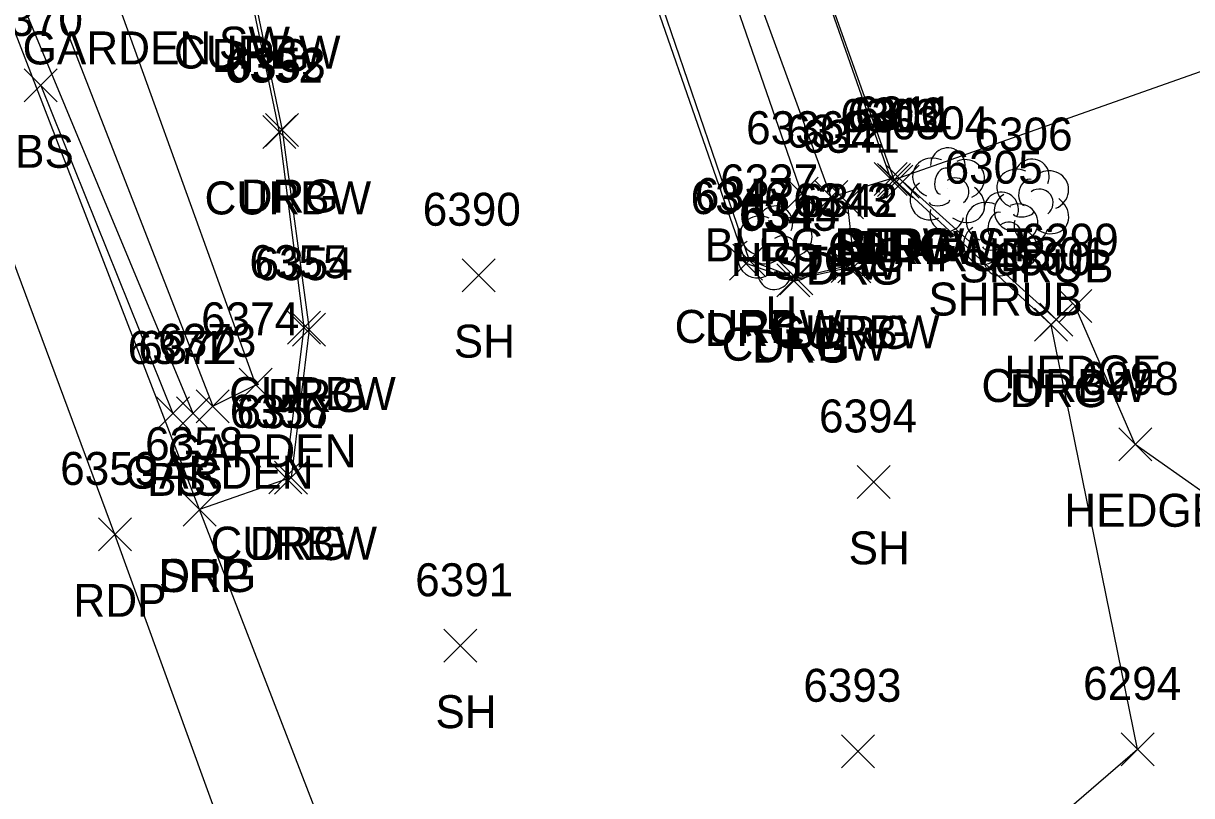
# Model space of a CAD drawing. Extents: x 1769141 to 1770911, y 735471 to 741449.
# Drawn here: x 1770299.5 to 1770370.4, y 740558.9 to 740605.8 of the extents above; entities that cross this region are included whole.
import ezdxf

# ---------------------------------------------------------------- set-up
doc = ezdxf.new("R2010")
doc.units = 0
for name, color, linetype in [('L_A', 7, 'Continuous'), ('L_I', 7, 'Continuous'), ('L_TIC', 7, 'Continuous'), ('LAHR', 7, 'Continuous'), ('LAPB', 7, 'Continuous'), ('LBC', 7, 'Continuous'), ('LBF', 7, 'Continuous'), ('LELB', 7, 'Continuous'), ('LSH', 7, 'Continuous'), ('LSOGP', 7, 'Continuous'), ('LTD', 7, 'Continuous'), ('P_A', 7, 'Continuous'), ('P_I', 7, 'Continuous'), ('P_TIC', 7, 'Continuous'), ('PET', 7, 'Continuous'), ('PSP', 7, 'Continuous'), ('R_A', 7, 'Continuous'), ('R_I', 7, 'Continuous'), ('R_TIC', 7, 'Continuous'), ('RC', 7, 'Continuous'), ('RDG', 7, 'Continuous')]:
    doc.layers.add(name, color=color, linetype=linetype)

msp = doc.modelspace()

# ---------------------------------------------------------------- linework, layer by layer
at = {"layer": 'L_TIC'}
for points in [[(1770299.573, 740601), (1770301.573, 740603)], [(1770301.573, 740601), (1770299.573, 740603)], [(1770351.112, 740595.326), (1770353.112, 740597.326)], [(1770353.112, 740595.326), (1770351.112, 740597.326)], [(1770351.112, 740595.326), (1770353.112, 740597.326)], [(1770353.112, 740595.326), (1770351.112, 740597.326)], [(1770351.319, 740595.262), (1770353.319, 740597.262)], [(1770353.319, 740595.262), (1770351.319, 740597.262)], [(1770345.708, 740594.432), (1770347.708, 740596.432)], [(1770347.708, 740594.432), (1770345.708, 740596.432)], [(1770347.511, 740594.223), (1770349.511, 740596.223)], [(1770349.511, 740594.223), (1770347.511, 740596.223)], [(1770326.129, 740589.486), (1770328.129, 740591.486)], [(1770328.129, 740589.486), (1770326.129, 740591.486)], [(1770362.306, 740587.614), (1770364.306, 740589.614)], [(1770364.306, 740587.614), (1770362.306, 740589.614)], [(1770312.605, 740582.838), (1770314.605, 740584.838)], [(1770314.605, 740582.838), (1770312.605, 740584.838)], [(1770310.001, 740581.536), (1770312.001, 740583.536)], [(1770312.001, 740581.536), (1770310.001, 740583.536)], [(1770307.585, 740581.101), (1770309.585, 740583.101)], [(1770309.585, 740581.101), (1770307.585, 740583.101)], [(1770308.796, 740581.109), (1770310.796, 740583.109)], [(1770310.796, 740581.109), (1770308.796, 740583.109)], [(1770365.938, 740579.227), (1770367.938, 740581.227)], [(1770367.938, 740579.227), (1770365.938, 740581.227)], [(1770350.071, 740576.947), (1770352.071, 740578.947)], [(1770352.071, 740576.947), (1770350.071, 740578.947)], [(1770325.018, 740567.011), (1770327.018, 740569.011)], [(1770327.018, 740567.011), (1770325.018, 740569.011)], [(1770349.121, 740560.611), (1770351.121, 740562.611)], [(1770351.121, 740560.611), (1770349.121, 740562.611)]]:
    msp.add_lwpolyline(points, dxfattribs=at)
at = {"layer": 'LAHR'}
for points in [[(1770339.44, 740616.413), (1770346.708, 740595.432)], [(1770381.293, 740570.108), (1770366.938, 740580.227), (1770363.306, 740588.614)]]:
    msp.add_lwpolyline(points, dxfattribs=at)
at = {"layer": 'LAPB'}
msp.add_lwpolyline([(1770292.169, 740641.437), (1770289.154, 740640.674), (1770298.462, 740614.818), (1770311.001, 740582.536), (1770313.605, 740583.838), (1770304.802, 740608.272), (1770322.28, 740615.018), (1770320.99, 740618.23), (1770303.138, 740612.542)], dxfattribs=at)
at = {"layer": 'LBC'}
msp.add_lwpolyline([(1770379.068, 740605.704), (1770352.319, 740596.262), (1770352.112, 740596.326), (1770340.804, 740628.648), (1770332.856, 740651.566), (1770359.461, 740660.913)], dxfattribs=at)
at = {"layer": 'LBF'}
msp.add_lwpolyline([(1770352.112, 740596.326), (1770348.511, 740595.223), (1770340.416, 740617.351), (1770339.502, 740617.408), (1770339.247, 740618.645), (1770334.568, 740617.183), (1770332.207, 740624.032), (1770336.61, 740625.673), (1770336.056, 740626.939), (1770340.804, 740628.648)], dxfattribs=at)
at = {"layer": 'LELB'}
for points in [[(1770296.256, 740614.633), (1770309.796, 740582.109)], [(1770300.573, 740602), (1770308.585, 740582.101)]]:
    msp.add_lwpolyline(points, dxfattribs=at)
at = {"layer": 'LSH'}
for p, q in [((1770355.53, 740595.726), (1770355.53, 740595.726)), ((1770355.53, 740595.726), (1770355.53, 740595.726)), ((1770360.633, 740595.048), (1770360.633, 740595.048)), ((1770360.633, 740595.048), (1770360.633, 740595.048)), ((1770358.769, 740593.039), (1770358.769, 740593.039)), ((1770358.769, 740593.039), (1770358.769, 740593.039))]:
    msp.add_line(p, q, dxfattribs=at)
for centre in [(1770355.577, 740597.16), (1770360.68, 740596.482), (1770358.816, 740594.473)]:
    msp.add_arc(centre, 1.047, 335.52715, 180.95627, dxfattribs=at)
for centre, major_axis, ratio, start_param, end_param in [((1770354.738, 740596.392), (1.21, -0.512), 0.895232, 1.570796, 4.712389), ((1770356.572, 740596.309), (-1.141, -0.483), 0.949671, 1.570796, 4.712389), ((1770355.322, 740596.184), (-0.208, -0.792), 0.645439, 3.141593, 6.283185), ((1770359.841, 740595.714), (1.21, -0.512), 0.895232, 1.570796, 4.712389), ((1770361.674, 740595.631), (-1.141, -0.483), 0.949671, 1.570796, 4.712389), ((1770354.447, 740595.017), (0.584, -1.042), 0.959034, 3.141593, 6.283185), ((1770356.03, 740595.559), (-0.5, 0.667), 0.989748, 3.141593, 6.283185), ((1770360.424, 740595.506), (-0.208, -0.792), 0.645439, 3.141593, 6.283185), ((1770356.53, 740594.893), (-1.09, 0.792), 0.841452, 1.570796, 4.712389), ((1770359.55, 740594.339), (0.584, -1.042), 0.959034, 3.141593, 6.283185), ((1770361.133, 740594.881), (-0.5, 0.667), 0.989748, 3.141593, 6.283185), ((1770355.072, 740594.976), (-0.625, -0.083), 0.423636, 0, 3.141593), ((1770357.977, 740593.706), (1.21, -0.512), 0.895232, 1.570796, 4.712389), ((1770359.811, 740593.623), (-1.141, -0.483), 0.949671, 1.570796, 4.712389), ((1770361.633, 740594.215), (-1.09, 0.792), 0.841452, 1.570796, 4.712389), ((1770355.53, 740594.226), (0.265, 1.061), 0.942809, 1.570796, 4.712389), ((1770358.561, 740593.498), (-0.208, -0.792), 0.645439, 3.141593, 6.283185), ((1770360.175, 740594.298), (-0.625, -0.083), 0.423636, 0, 3.141593), ((1770357.686, 740592.331), (0.584, -1.042), 0.959034, 3.141593, 6.283185), ((1770359.269, 740592.873), (-0.5, 0.667), 0.989748, 3.141593, 6.283185), ((1770360.633, 740593.548), (0.265, 1.061), 0.942809, 1.570796, 4.712389), ((1770359.769, 740592.206), (-1.09, 0.792), 0.841452, 1.570796, 4.712389), ((1770358.311, 740592.289), (-0.625, -0.083), 0.423636, 0, 3.141593), ((1770358.769, 740591.539), (0.265, 1.061), 0.942809, 1.570796, 4.712389)]:
    msp.add_ellipse(centre, major_axis=major_axis, ratio=ratio, start_param=start_param, end_param=end_param, dxfattribs=at)
at = {"layer": 'LSOGP'}
msp.add_lwpolyline([(1770461.262, 740381.755), (1770439.599, 740402.542), (1770418.832, 740437.32), (1770419.836, 740449.336), (1770418.641, 740453.197), (1770389.387, 740520.522), (1770396.773, 740524.961), (1770394.624, 740537.746), (1770388.146, 740554.187), (1770389.154, 740577.288), (1770388.464, 740577.65), (1770384.924, 740591.99), (1770379.068, 740605.704), (1770352.319, 740596.262), (1770340.804, 740628.648), (1770332.856, 740651.566), (1770359.461, 740660.913), (1770352.204, 740662.233), (1770351.852, 740662.515), (1770349.119, 740679.451)], dxfattribs=at)
at = {"layer": 'LTD'}
msp.add_line((1770345.076, 740592.206), (1770345.076, 740592.206), dxfattribs=at)
msp.add_line((1770345.076, 740592.206), (1770345.076, 740592.206), dxfattribs=at)
msp.add_arc((1770345.123, 740593.64), 1.047, 335.52715, 180.95627, dxfattribs=at)
for centre, major_axis, ratio, start_param, end_param in [((1770344.284, 740592.872), (1.21, -0.512), 0.895232, 1.570796, 4.712389), ((1770346.118, 740592.789), (-1.141, -0.483), 0.949671, 1.570796, 4.712389), ((1770344.868, 740592.664), (-0.208, -0.792), 0.645439, 3.141593, 6.283185), ((1770343.993, 740591.497), (0.584, -1.042), 0.959034, 3.141593, 6.283185), ((1770345.576, 740592.039), (-0.5, 0.667), 0.989748, 3.141593, 6.283185), ((1770346.076, 740591.373), (-1.09, 0.792), 0.841452, 1.570796, 4.712389), ((1770344.618, 740591.456), (-0.625, -0.083), 0.423636, 0, 3.141593), ((1770345.076, 740590.706), (0.265, 1.061), 0.942809, 1.570796, 4.712389)]:
    msp.add_ellipse(centre, major_axis=major_axis, ratio=ratio, start_param=start_param, end_param=end_param, dxfattribs=at)
at = {"layer": 'P_TIC'}
for points in [[(1770309.208, 740575.265), (1770311.208, 740577.265)], [(1770311.208, 740575.265), (1770309.208, 740577.265)], [(1770304.065, 740573.764), (1770306.065, 740575.764)], [(1770306.065, 740573.764), (1770304.065, 740575.764)]]:
    msp.add_lwpolyline(points, dxfattribs=at)
at = {"layer": 'PET'}
msp.add_lwpolyline([(1770379.157, 740373.294), (1770360.22, 740424.507), (1770338.77, 740482.71), (1770320.682, 740531.701), (1770305.065, 740574.764), (1770283.592, 740632.55), (1770262.079, 740689.358), (1770241.573, 740741.187), (1770220.778, 740793.369), (1770202.074, 740839.631), (1770179.173, 740893.092)], dxfattribs=at)
at = {"layer": 'PSP'}
msp.add_lwpolyline([(1770540.34, 739951.651), (1770528.662, 739983.215), (1770504.989, 740047.845), (1770496.224, 740070.804), (1770481.818, 740111.557), (1770464.171, 740161.253), (1770449.881, 740201.401), (1770429.298, 740252.9), (1770418.044, 740283.828), (1770400.744, 740330.551), (1770384.345, 740374.743), (1770365.927, 740426.732), (1770363.005, 740434.142), (1770343.366, 740484.075), (1770326.568, 740533.853), (1770310.208, 740576.265), (1770285.85, 740639.316), (1770267.253, 740691.654), (1770245.277, 740742.415), (1770222.401, 740793.584), (1770203.844, 740840.26), (1770179.151, 740903.218)], dxfattribs=at)
at = {"layer": 'R_TIC'}
for points in [[(1770314.039, 740598.172), (1770316.039, 740600.172)], [(1770316.039, 740598.172), (1770314.039, 740600.172)], [(1770314.206, 740598.287), (1770316.206, 740600.287)], [(1770316.206, 740598.287), (1770314.206, 740600.287)], [(1770351.445, 740595.17), (1770353.445, 740597.17)], [(1770353.445, 740595.17), (1770351.445, 740597.17)], [(1770351.845, 740595.162), (1770353.845, 740597.162)], [(1770353.845, 740595.162), (1770351.845, 740597.162)], [(1770348.464, 740593.911), (1770350.464, 740595.911)], [(1770350.464, 740593.911), (1770348.464, 740595.911)], [(1770342.341, 740590.193), (1770344.341, 740592.193)], [(1770344.341, 740590.193), (1770342.341, 740592.193)], [(1770342.543, 740590.378), (1770344.543, 740592.378)], [(1770344.543, 740590.378), (1770342.543, 740592.378)], [(1770348.507, 740590.05), (1770350.507, 740592.05)], [(1770350.507, 740590.05), (1770348.507, 740592.05)], [(1770348.904, 740590.016), (1770350.904, 740592.016)], [(1770350.904, 740590.016), (1770348.904, 740592.016)], [(1770345.214, 740589.179), (1770347.214, 740591.179)], [(1770347.214, 740589.179), (1770345.214, 740591.179)], [(1770345.391, 740589.299), (1770347.391, 740591.299)], [(1770347.391, 740589.299), (1770345.391, 740591.299)], [(1770315.533, 740586.306), (1770317.533, 740588.306)], [(1770317.533, 740586.306), (1770315.533, 740588.306)], [(1770360.841, 740586.482), (1770362.841, 740588.482)], [(1770362.841, 740586.482), (1770360.841, 740588.482)], [(1770361.151, 740586.792), (1770363.151, 740588.792)], [(1770363.151, 740586.792), (1770361.151, 740588.792)], [(1770315.848, 740586.185), (1770317.848, 740588.185)], [(1770317.848, 740586.185), (1770315.848, 740588.185)], [(1770314.397, 740577.234), (1770316.397, 740579.234)], [(1770316.397, 740577.234), (1770314.397, 740579.234)], [(1770314.748, 740577.206), (1770316.748, 740579.206)], [(1770316.748, 740577.206), (1770314.748, 740579.206)], [(1770309.208, 740575.265), (1770311.208, 740577.265)], [(1770311.208, 740575.265), (1770309.208, 740577.265)], [(1770366.088, 740560.728), (1770368.088, 740562.728)], [(1770368.088, 740560.728), (1770366.088, 740562.728)]]:
    msp.add_lwpolyline(points, dxfattribs=at)
at = {"layer": 'RC'}
for points in [[(1770349.507, 740591.05), (1770346.391, 740590.299), (1770343.543, 740591.378), (1770335.315, 740615.423), (1770313.185, 740608.02), (1770315.039, 740599.172), (1770316.533, 740587.306), (1770315.397, 740578.234)], [(1770362.151, 740587.792), (1770352.845, 740596.162)]]:
    msp.add_lwpolyline(points, dxfattribs=at)
at = {"layer": 'RDG'}
for points in [[(1770349.464, 740594.911), (1770349.904, 740591.016), (1770346.214, 740590.179), (1770343.341, 740591.193), (1770335.033, 740615.113), (1770313.442, 740607.815), (1770315.206, 740599.287), (1770316.848, 740587.185), (1770315.748, 740578.206), (1770310.208, 740576.265)], [(1770336.34, 740537.078), (1770351.837, 740548.576), (1770367.088, 740561.728), (1770361.841, 740587.482), (1770352.445, 740596.17)]]:
    msp.add_lwpolyline(points, dxfattribs=at)

# ---------------------------------------------------------------- texts
at = {"layer": 'L_A'}
for s, p in [('GARDEN', (1770299.471, 740603.272)), ('BS', (1770299.014, 740597)), ('BLDG STPW ST', (1770340.828, 740591.326)), ('BLDG', (1770348.702, 740591.326)), ('BLDG', (1770348.909, 740591.262)), ('SHRUB', (1770351.16, 740590.726)), ('HEDGE', (1770342.409, 740590.432)), ('STPW', (1770344.905, 740590.223)), ('SHRUB', (1770356.263, 740590.048)), ('SHRUB', (1770354.399, 740588.039)), ('H', (1770344.509, 740587.206)), ('SH', (1770325.617, 740585.486)), ('HEDGE', (1770359.007, 740583.614)), ('GARDEN', (1770308.274, 740578.838)), ('GARDEN', (1770305.67, 740577.536)), ('BS', (1770307.026, 740577.101)), ('TS', (1770308.206, 740577.109)), ('HEDGE', (1770362.639, 740575.227)), ('SH', (1770349.559, 740572.947)), ('SH', (1770324.506, 740563.011))]:
    msp.add_text(s, height=2, dxfattribs=at).set_placement(p)
at = {"layer": 'L_I'}
for s, p in [('6370', (1770297.179, 740605)), ('6310', (1770349.492, 740599.262)), ('6311', (1770349.939, 740599.326)), ('6311', (1770349.939, 740599.326)), ('6336', (1770343.346, 740598.432)), ('6304', (1770352.144, 740598.726)), ('6312', (1770345.771, 740598.223)), ('6306', (1770357.192, 740598.048)), ('6305', (1770355.383, 740596.039)), ('6337', (1770341.769, 740595.206)), ('6390', (1770323.735, 740593.486)), ('6299', (1770359.991, 740591.614)), ('6374', (1770310.298, 740586.838)), ('6373', (1770307.694, 740585.536)), ('6371', (1770305.845, 740585.101)), ('6372', (1770306.489, 740585.109)), ('6298', (1770363.631, 740583.227)), ('6394', (1770347.764, 740580.947)), ('6391', (1770323.278, 740571.011)), ('6393', (1770346.814, 740564.611))]:
    msp.add_text(s, height=2, dxfattribs=at).set_placement(p)
at = {"layer": 'P_A'}
for s, p in [('SHP', (1770307.743, 740571.265)), ('RDP', (1770302.553, 740569.764))]:
    msp.add_text(s, height=2, dxfattribs=at).set_placement(p)
at = {"layer": 'P_I'}
for s, p in [('6358', (1770306.901, 740579.265)), ('6359', (1770301.75, 740577.764))]:
    msp.add_text(s, height=2, dxfattribs=at).set_placement(p)
at = {"layer": 'R_A'}
for s, p in [('SW', (1770311.378, 740603.562)), ('CURBW', (1770308.649, 740603.02)), ('DRG', (1770310.93, 740602.815)), ('CURBW', (1770310.504, 740594.172)), ('DRG', (1770312.694, 740594.287)), ('CURBW', (1770348.309, 740591.162)), ('DRG', (1770349.933, 740591.17)), ('DRG', (1770346.952, 740589.911)), ('CURBW', (1770339.008, 740586.378)), ('DRG', (1770340.829, 740586.193)), ('CURBW', (1770344.972, 740586.05)), ('DRG', (1770347.392, 740586.016)), ('CURBW', (1770341.856, 740585.299)), ('DRG', (1770343.702, 740585.179)), ('CURBW', (1770357.615, 740582.792)), ('CURBW', (1770311.998, 740582.306)), ('DRG', (1770314.336, 740582.185)), ('DRG', (1770359.329, 740582.482)), ('CURBW', (1770310.862, 740573.234)), ('DRG', (1770313.236, 740573.206)), ('DRG', (1770307.696, 740571.265))]:
    msp.add_text(s, height=2, dxfattribs=at).set_placement(p)
at = {"layer": 'R_I'}
for s, p in [('6352', (1770311.732, 740602.172)), ('6353', (1770311.899, 740602.287)), ('6303', (1770349.059, 740599.17)), ('6302', (1770349.459, 740599.162)), ('6341', (1770346.724, 740597.911)), ('6346', (1770339.979, 740594.193)), ('6347', (1770340.236, 740594.378)), ('6343', (1770346.2, 740594.05)), ('6342', (1770346.597, 740594.016)), ('6345', (1770342.907, 740593.179)), ('6344', (1770343.084, 740593.299)), ('6300', (1770358.369, 740590.482)), ('6301', (1770359.332, 740590.792)), ('6355', (1770313.226, 740590.306)), ('6354', (1770313.541, 740590.185)), ('6356', (1770312.035, 740581.234)), ('6357', (1770312.441, 740581.206)), ('6358', (1770306.901, 740579.265)), ('6294', (1770363.781, 740564.728))]:
    msp.add_text(s, height=2, dxfattribs=at).set_placement(p)

doc.saveas('drawing.dxf')
